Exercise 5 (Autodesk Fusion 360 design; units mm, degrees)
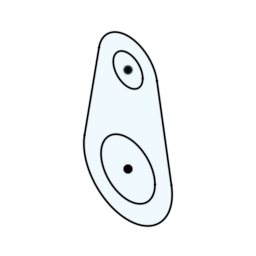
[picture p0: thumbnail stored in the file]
sketch "Sketch1" plane through (0, 0, 0) normal (0, 1, 0) x axis (1, 0, 0)
  line L1 (-17.7335, -3.0857) -> (-11.8224, -37.0571)
  line L2 (17.7335, -3.0857) -> (11.8224, -37.0571)
  circle C1 centre (0, 0) radius 11
  circle C2 centre (0, -35) radius 6
  arc A1 centre (0, -35) radius 12 clockwise from (11.8224, -37.0571) to (-11.8224, -37.0571)
  arc A2 centre (0, 0) radius 18 clockwise from (-17.7335, -3.0857) to (17.7335, -3.0857)
  point P1 (0, 0)
  point P2 (0, 0)
  point P3 (0, 0)
  point P5 (0, -35)
  coincident P1 P2
  concentric C1 A2
  concentric C2 A1
  tangent L1 A2
  tangent L2 A2
  tangent L1 A1
  tangent L2 A1
  vertical P3 P5
  dimension "d1" diameter C1 = 22
  dimension "d4" distance P3 P5 = 35
  dimension "d5" diameter C2 = 12
  dimension "d6" radius A1 = 12
  dimension "d7" radius A2 = 18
